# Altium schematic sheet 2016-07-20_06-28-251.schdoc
size 292 x 119 mm; SheetNumber: 1; SheetTotal: 1
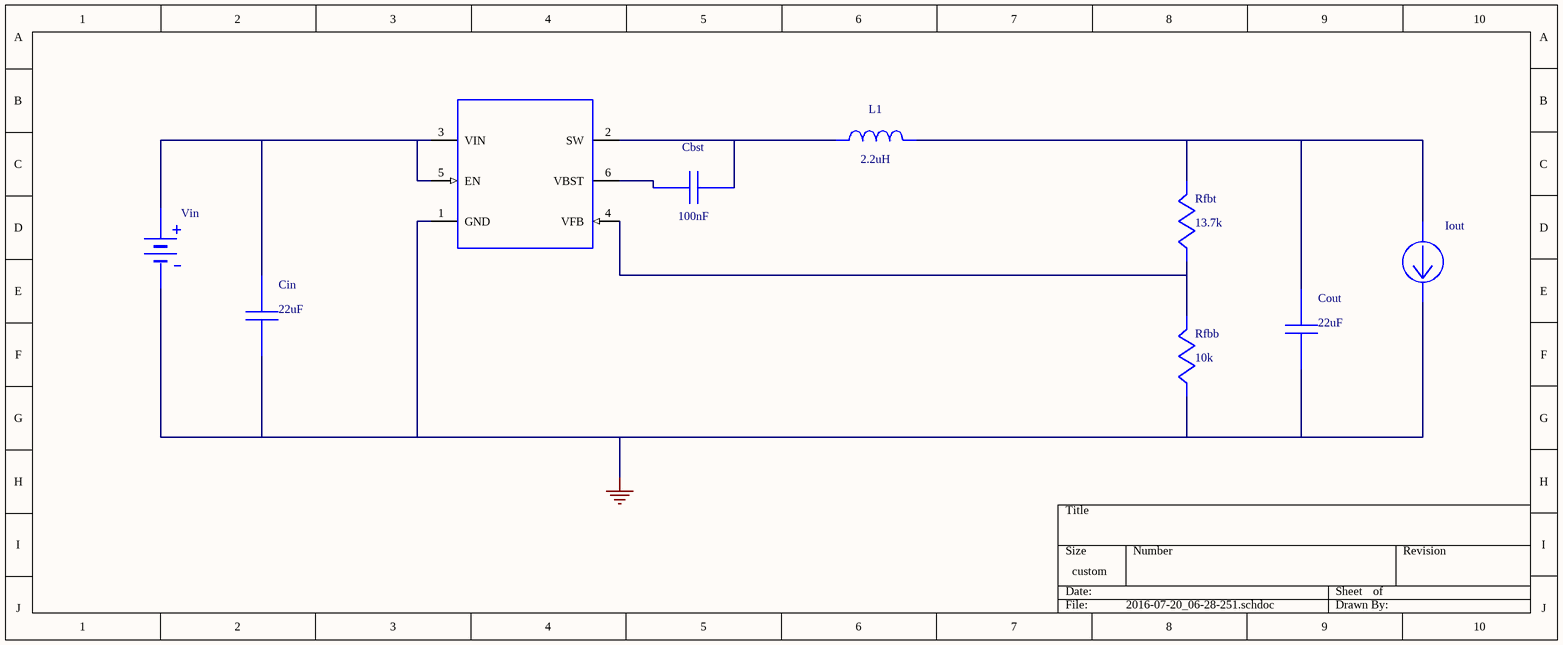
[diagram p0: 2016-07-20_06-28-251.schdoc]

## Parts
Cbst  value 100nF  (hidden comment: 08053C104KAT2A)
Cin  value 22uF  (hidden comment: GRM31CR61A226KE19L)
Cout  value 22uF  (hidden comment: GRM21BC80G226ME39L)
Iout  WB_CURRENT_LOAD  (value not drawn)
L1  value 2.2uH  (hidden comment: 'VLF403215MT-2R2M')
Rfbb  value 10k  (hidden comment: CRCW040210K0FKED)
Rfbt  value 13.7k  (hidden comment: CRCW040213K7FKED)
U1  TPS562200DDCR  (value not drawn)
Vin  WB_BATTERY  (value not drawn)

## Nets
0: Cin.2 Cout.2 Iout.2(-) Rfbb.2 U1.1(GND) Vin.2(-)
NetCbst_1: Cbst.1 L1.1 U1.2(SW)
NetCbst_2: Cbst.2 U1.6(VBST)
NetCin_1: Cin.1 U1.3(VIN) U1.5(EN) Vin.1(+)
NetCout_1: Cout.1 Iout.1(+) L1.2 Rfbt.1
NetRfbb_1: Rfbb.1 Rfbt.2 U1.4(VFB)

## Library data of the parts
Cbst = 08053C104KAT2A: Manufacturer Name: AVX
Cin = GRM31CR61A226KE19L: GRM31CR61A226KE1; Manufacturer Name: MuRata
Cout = GRM21BC80G226ME39L: GRM21BC80G226ME3; Manufacturer Name: MuRata
L1 = 'VLF403215MT-2R2M': VLF403215MT-2R2M; Manufacturer Name: TDK
Rfbb = CRCW040210K0FKED: Manufacturer Name: Vishay-Dale
Rfbt = CRCW040213K7FKED: Manufacturer Name: Vishay-Dale
U1 = TPS562200DDCR: Manufacturer Name: Texas Instruments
